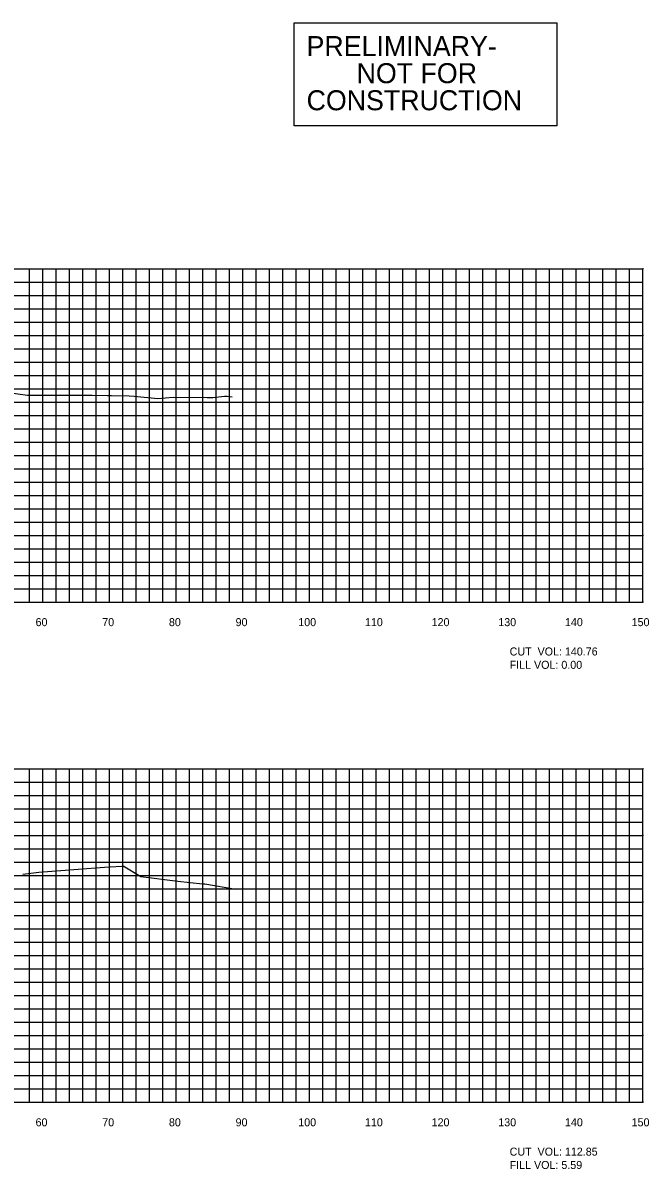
# Model space of a CAD drawing. Extents: x 1800880 to 1814006, y 250083 to 250560.
# Drawn here: x 1813228 to 1813321.9, y 250089.4 to 250261.3 of the extents above; entities that cross this region are included whole.
import ezdxf

# ---------------------------------------------------------------- set-up
doc = ezdxf.new("R2010")
doc.units = 0
for name, color, linetype in [('CL-CNST', 7, 'Continuous'), ('DESIGN - DRAINAGE - Bridges', 7, 'Continuous'), ('DRAINAGETXT', 7, 'Continuous'), ('Level 32', 7, 'Continuous'), ('Level 46', 7, 'Continuous')]:
    doc.layers.add(name, color=color, linetype=linetype)

msp = doc.modelspace()

# ---------------------------------------------------------------- linework, layer by layer
at = {"layer": 'CL-CNST'}
for points in [[(1813225.79, 250205.88), (1813228.69, 250205.49), (1813229.24, 250205.48), (1813229.35, 250205.48), (1813230.61, 250205.46), (1813231.26, 250205.46), (1813238.41, 250205.45), (1813240.7, 250205.43), (1813240.92, 250205.43), (1813241.3, 250205.43), (1813243.95, 250205.35), (1813244.67, 250205.3), (1813248.26, 250204.96), (1813250.53, 250205.16), (1813255.66, 250205.13), (1813255.83, 250205.13), (1813256.29, 250205.13), (1813256.51, 250205.14), (1813258.25, 250205.3), (1813258.36, 250205.33), (1813258.62, 250205.33), (1813259.38, 250205.2)], [(1813227.99, 250133.63), (1813230.39, 250133.92), (1813240.87, 250134.73), (1813241.09, 250134.74), (1813242.82, 250134.86), (1813243.05, 250134.88), (1813245.69, 250133.29), (1813251.23, 250132.59), (1813254.95, 250132.17), (1813255.09, 250132.17), (1813255.31, 250132.17), (1813259.93, 250131.4)]]:
    msp.add_lwpolyline(points, dxfattribs=at)
at = {"layer": 'DESIGN - DRAINAGE - Bridges'}
for p, q in [((1813321, 250174.43), (1813321, 250224.43)), ((1813321.06, 250224.43), (1813321, 250224.43)), ((1813321.06, 250214.43), (1813321, 250214.43)), ((1813321.06, 250204.43), (1813321, 250204.43)), ((1813321.06, 250194.43), (1813321, 250194.43)), ((1813321.06, 250184.43), (1813321, 250184.43)), ((1813021, 250174.43), (1813321, 250174.43)), ((1813231, 250174.37), (1813231, 250174.43)), ((1813241, 250174.37), (1813241, 250174.43)), ((1813251, 250174.37), (1813251, 250174.43)), ((1813261, 250174.37), (1813261, 250174.43)), ((1813271, 250174.37), (1813271, 250174.43)), ((1813281, 250174.37), (1813281, 250174.43)), ((1813291, 250174.37), (1813291, 250174.43)), ((1813301, 250174.37), (1813301, 250174.43)), ((1813311, 250174.37), (1813311, 250174.43)), ((1813321, 250174.37), (1813321, 250174.43)), ((1813321.06, 250174.43), (1813321, 250174.43)), ((1813321, 250099.43), (1813321, 250149.43)), ((1813321.06, 250149.43), (1813321, 250149.43)), ((1813321.06, 250139.43), (1813321, 250139.43)), ((1813321.06, 250129.43), (1813321, 250129.43)), ((1813321.06, 250119.43), (1813321, 250119.43)), ((1813321.06, 250109.43), (1813321, 250109.43)), ((1813021, 250099.43), (1813321, 250099.43)), ((1813231, 250099.37), (1813231, 250099.43)), ((1813241, 250099.37), (1813241, 250099.43)), ((1813251, 250099.37), (1813251, 250099.43)), ((1813261, 250099.37), (1813261, 250099.43)), ((1813271, 250099.37), (1813271, 250099.43)), ((1813281, 250099.37), (1813281, 250099.43)), ((1813291, 250099.37), (1813291, 250099.43)), ((1813301, 250099.37), (1813301, 250099.43)), ((1813311, 250099.37), (1813311, 250099.43)), ((1813321, 250099.37), (1813321, 250099.43)), ((1813321.06, 250099.43), (1813321, 250099.43))]:
    msp.add_line(p, q, dxfattribs=at)
at = {"layer": 'Level 32'}
msp.add_lwpolyline([(1813268.68, 250261.29), (1813308.08, 250261.29), (1813308.08, 250245.85), (1813268.68, 250245.85)], close=True, dxfattribs=at)
at = {"layer": 'Level 46'}
for p, q in [((1813021, 250224.43), (1813321, 250224.43)), ((1813229, 250174.43), (1813229, 250224.43)), ((1813231, 250174.43), (1813231, 250224.43)), ((1813233, 250174.43), (1813233, 250224.43)), ((1813235, 250174.43), (1813235, 250224.43)), ((1813237, 250174.43), (1813237, 250224.43)), ((1813239, 250174.43), (1813239, 250224.43)), ((1813241, 250174.43), (1813241, 250224.43)), ((1813243, 250174.43), (1813243, 250224.43)), ((1813245, 250174.43), (1813245, 250224.43)), ((1813247, 250174.43), (1813247, 250224.43)), ((1813249, 250174.43), (1813249, 250224.43)), ((1813251, 250174.43), (1813251, 250224.43)), ((1813253, 250174.43), (1813253, 250224.43)), ((1813255, 250174.43), (1813255, 250224.43)), ((1813257, 250174.43), (1813257, 250224.43)), ((1813259, 250174.43), (1813259, 250224.43)), ((1813261, 250174.43), (1813261, 250224.43)), ((1813263, 250174.43), (1813263, 250224.43)), ((1813265, 250174.43), (1813265, 250224.43)), ((1813267, 250174.43), (1813267, 250224.43)), ((1813269, 250174.43), (1813269, 250224.43)), ((1813271, 250174.43), (1813271, 250224.43)), ((1813273, 250174.43), (1813273, 250224.43)), ((1813275, 250174.43), (1813275, 250224.43)), ((1813277, 250174.43), (1813277, 250224.43)), ((1813279, 250174.43), (1813279, 250224.43)), ((1813281, 250174.43), (1813281, 250224.43)), ((1813283, 250174.43), (1813283, 250224.43)), ((1813285, 250174.43), (1813285, 250224.43)), ((1813287, 250174.43), (1813287, 250224.43)), ((1813289, 250174.43), (1813289, 250224.43)), ((1813291, 250174.43), (1813291, 250224.43)), ((1813293, 250174.43), (1813293, 250224.43)), ((1813295, 250174.43), (1813295, 250224.43)), ((1813297, 250174.43), (1813297, 250224.43)), ((1813299, 250174.43), (1813299, 250224.43)), ((1813301, 250174.43), (1813301, 250224.43)), ((1813303, 250174.43), (1813303, 250224.43)), ((1813305, 250174.43), (1813305, 250224.43)), ((1813307, 250174.43), (1813307, 250224.43)), ((1813309, 250174.43), (1813309, 250224.43)), ((1813311, 250174.43), (1813311, 250224.43)), ((1813313, 250174.43), (1813313, 250224.43)), ((1813315, 250174.43), (1813315, 250224.43)), ((1813317, 250174.43), (1813317, 250224.43)), ((1813319, 250174.43), (1813319, 250224.43)), ((1813321, 250174.43), (1813321, 250224.43)), ((1813021, 250222.43), (1813321, 250222.43)), ((1813021, 250220.43), (1813321, 250220.43)), ((1813021, 250218.43), (1813321, 250218.43)), ((1813021, 250216.43), (1813321, 250216.43)), ((1813021, 250214.43), (1813321, 250214.43)), ((1813021, 250212.43), (1813321, 250212.43)), ((1813021, 250210.43), (1813321, 250210.43)), ((1813021, 250208.43), (1813321, 250208.43)), ((1813021, 250206.43), (1813321, 250206.43)), ((1813021, 250204.43), (1813321, 250204.43)), ((1813021, 250202.43), (1813321, 250202.43)), ((1813021, 250200.43), (1813321, 250200.43)), ((1813021, 250198.43), (1813321, 250198.43)), ((1813021, 250196.43), (1813321, 250196.43)), ((1813021, 250194.43), (1813321, 250194.43)), ((1813021, 250192.43), (1813321, 250192.43)), ((1813021, 250190.43), (1813321, 250190.43)), ((1813021, 250188.43), (1813321, 250188.43)), ((1813021, 250186.43), (1813321, 250186.43)), ((1813021, 250184.43), (1813321, 250184.43)), ((1813021, 250182.43), (1813321, 250182.43)), ((1813021, 250180.43), (1813321, 250180.43)), ((1813021, 250178.43), (1813321, 250178.43)), ((1813021, 250176.43), (1813321, 250176.43)), ((1813021, 250174.43), (1813321, 250174.43)), ((1813021, 250149.43), (1813321, 250149.43)), ((1813229, 250099.43), (1813229, 250149.43)), ((1813231, 250099.43), (1813231, 250149.43)), ((1813233, 250099.43), (1813233, 250149.43)), ((1813235, 250099.43), (1813235, 250149.43)), ((1813237, 250099.43), (1813237, 250149.43)), ((1813239, 250099.43), (1813239, 250149.43)), ((1813241, 250099.43), (1813241, 250149.43)), ((1813243, 250099.43), (1813243, 250149.43)), ((1813245, 250099.43), (1813245, 250149.43)), ((1813247, 250099.43), (1813247, 250149.43)), ((1813249, 250099.43), (1813249, 250149.43)), ((1813251, 250099.43), (1813251, 250149.43)), ((1813253, 250099.43), (1813253, 250149.43)), ((1813255, 250099.43), (1813255, 250149.43)), ((1813257, 250099.43), (1813257, 250149.43)), ((1813259, 250099.43), (1813259, 250149.43)), ((1813261, 250099.43), (1813261, 250149.43)), ((1813263, 250099.43), (1813263, 250149.43)), ((1813265, 250099.43), (1813265, 250149.43)), ((1813267, 250099.43), (1813267, 250149.43)), ((1813269, 250099.43), (1813269, 250149.43)), ((1813271, 250099.43), (1813271, 250149.43)), ((1813273, 250099.43), (1813273, 250149.43)), ((1813275, 250099.43), (1813275, 250149.43)), ((1813277, 250099.43), (1813277, 250149.43)), ((1813279, 250099.43), (1813279, 250149.43)), ((1813281, 250099.43), (1813281, 250149.43)), ((1813283, 250099.43), (1813283, 250149.43)), ((1813285, 250099.43), (1813285, 250149.43)), ((1813287, 250099.43), (1813287, 250149.43)), ((1813289, 250099.43), (1813289, 250149.43)), ((1813291, 250099.43), (1813291, 250149.43)), ((1813293, 250099.43), (1813293, 250149.43)), ((1813295, 250099.43), (1813295, 250149.43)), ((1813297, 250099.43), (1813297, 250149.43)), ((1813299, 250099.43), (1813299, 250149.43)), ((1813301, 250099.43), (1813301, 250149.43)), ((1813303, 250099.43), (1813303, 250149.43)), ((1813305, 250099.43), (1813305, 250149.43)), ((1813307, 250099.43), (1813307, 250149.43)), ((1813309, 250099.43), (1813309, 250149.43)), ((1813311, 250099.43), (1813311, 250149.43)), ((1813313, 250099.43), (1813313, 250149.43)), ((1813315, 250099.43), (1813315, 250149.43)), ((1813317, 250099.43), (1813317, 250149.43)), ((1813319, 250099.43), (1813319, 250149.43)), ((1813321, 250099.43), (1813321, 250149.43)), ((1813021, 250147.43), (1813321, 250147.43)), ((1813021, 250145.43), (1813321, 250145.43)), ((1813021, 250143.43), (1813321, 250143.43)), ((1813021, 250141.43), (1813321, 250141.43)), ((1813021, 250139.43), (1813321, 250139.43)), ((1813021, 250137.43), (1813321, 250137.43)), ((1813021, 250135.43), (1813321, 250135.43)), ((1813021, 250133.43), (1813321, 250133.43)), ((1813021, 250131.43), (1813321, 250131.43)), ((1813021, 250129.43), (1813321, 250129.43)), ((1813021, 250127.43), (1813321, 250127.43)), ((1813021, 250125.43), (1813321, 250125.43)), ((1813021, 250123.43), (1813321, 250123.43)), ((1813021, 250121.43), (1813321, 250121.43)), ((1813021, 250119.43), (1813321, 250119.43)), ((1813021, 250117.43), (1813321, 250117.43)), ((1813021, 250115.43), (1813321, 250115.43)), ((1813021, 250113.43), (1813321, 250113.43)), ((1813021, 250111.43), (1813321, 250111.43)), ((1813021, 250109.43), (1813321, 250109.43)), ((1813021, 250107.43), (1813321, 250107.43)), ((1813021, 250105.43), (1813321, 250105.43)), ((1813021, 250103.43), (1813321, 250103.43)), ((1813021, 250101.43), (1813321, 250101.43)), ((1813021, 250099.43), (1813321, 250099.43))]:
    msp.add_line(p, q, dxfattribs=at)

# ---------------------------------------------------------------- texts
for s, p in [('60', (1813229.9, 250170.83)), ('70', (1813239.9, 250170.83)), ('80', (1813249.9, 250170.83)), ('90', (1813259.9, 250170.83)), ('100', (1813269.3, 250170.83)), ('110', (1813279.3, 250170.83)), ('120', (1813289.3, 250170.83)), ('130', (1813299.3, 250170.83)), ('140', (1813309.3, 250170.83)), ('150', (1813319.3, 250170.83)), ('60', (1813229.9, 250095.83)), ('70', (1813239.9, 250095.83)), ('80', (1813249.9, 250095.83)), ('90', (1813259.9, 250095.83)), ('100', (1813269.3, 250095.83)), ('110', (1813279.3, 250095.83)), ('120', (1813289.3, 250095.83)), ('130', (1813299.3, 250095.83)), ('140', (1813309.3, 250095.83)), ('150', (1813319.3, 250095.83))]:
    msp.add_text(s, height=1.2).set_placement(p)
at = {"layer": 'DRAINAGETXT'}
for s, p in [('CUT  VOL: 140.76', (1813301, 250166.43)), ('FILL VOL: 0.00', (1813301, 250164.43)), ('CUT  VOL: 112.85', (1813301, 250091.43)), ('FILL VOL: 5.59', (1813301, 250089.43))]:
    msp.add_text(s, height=1.2, dxfattribs=at).set_placement(p)
at = {"layer": 'Level 32'}
for s, p in [('PRELIMINARY-', (1813270.54, 250256.31)), ('NOT FOR', (1813278.05, 250252.25)), ('CONSTRUCTION', (1813270.55, 250248.19))]:
    msp.add_text(s, height=3, dxfattribs=at).set_placement(p)

doc.saveas('drawing.dxf')
